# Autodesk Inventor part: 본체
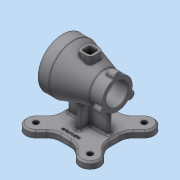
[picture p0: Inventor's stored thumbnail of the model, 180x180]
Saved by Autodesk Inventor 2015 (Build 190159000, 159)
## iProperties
Created: 2018-03
Part Number: 본체
Material: 일반
Document SubType Name: Modeling
Designer: SCD-A03
Density: 1 g/cm^3
Appearance: 기본값
Author: SCD-A03
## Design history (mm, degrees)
sketch "스케치1"
  geometry: L1 (50, 0)-(50, 45); L2 (50, 45)-(30, 45); L3 (30, 45)-(-27, 27.5); L4 (-50, 0)-(-50, 27.5); L5 (-27, 27.5)-(-50, 27.5); L6 (50, 0)-(-50, 0); L7 (0, 0)-(0, 7.405)
  constraints: 14 end point, 3 vertical, 2 horizontal, 1 perpendicular, 1 other
  dimensions: "d0" = 45 distance of L1.start L1.end; "d1" = 20 distance of L1.end L2.end; "d10" = 27.5 distance of L4.start L4.end; "d11" = 77 distance from line of L3.end L1; "d12" = 100 distance from line of L4.end L1; "d13" = 45 distance from line of L7.start L2; "d14" = 37.59532 distance from line of L7.end L2
revolve "회전1" sketch "스케치1" stored, may be unused: angle "d15" = 90 deg
node "작업 평면1"
sketch "스케치2"
  geometry: L1 (-19.544, 45)-(19.544, 45); L2 (45, 19.544)-(45, -19.544); L3 (-36.77, -36.77)-(-45, -45); L4 (-62.225, -36.77)-(-45, -19.544); L5 (19.544, 45)-(36.77, 62.225); L6 (-36.77, -62.225)-(-19.544, -45); L7 (45, 19.544)-(62.225, 36.77); L8 (45, 45)-(57.655, 57.655); L9 (-45, -45)-(-45, -32.068); L10 (-45, -19.544)-(-45, 19.544); L11 (-32.068, -45)-(-45, -45); L12 (62.225, -36.77)-(45, -19.544); L13 (-19.544, 45)-(-36.77, 62.225); L14 (45, -45)-(36.77, -36.77); L15 (-49.497, 49.497)-(-57.655, 57.655); L16 (36.77, -62.225)-(19.544, -45); L17 (-45, 19.544)-(-62.225, 36.77); L18 (-36.77, -36.77)-(-49.497, -49.497); L19 (-45, -45)-(-36.77, -36.77); L20 (45, -45)-(32.068, -45); L21 (19.544, -45)-(-19.544, -45); A1 r 18 centre (49.497, 49.497) between (62.225, 36.77) and (36.77, 62.225); A2 r 18 centre (49.497, -49.497) between (36.77, -62.225) and (62.225, -36.77); A3 r 18 centre (-49.497, 49.497) between (-36.77, 62.225) and (-62.225, 36.77); A4 r 18 centre (-49.497, -49.497) between (-62.225, -36.77) and (-36.77, -62.225); 1 further point
  constraints: 42 end point, 21 parallel, 8 point on circle, 4 centre point, 3 point on line, 1 coincident, 1 horizontal, 1 perpendicular
  dimensions: "d17" = 90 distance of L14.start L3.end; "d18" = 90 distance of L8.start L14.start; "d20" = 36 diameter of A1; "d25" = 36 diameter of A2
extrude "돌출1" join sketch "스케치2" distance "d28" = 12; taper "d29" = 0 deg
node "작업 평면2"
sketch "스케치3"
  geometry: L1 (-12.5, 12.5)-(12.5, 12.5); L2 (12.5, 12.5)-(12.5, -12.5); L3 (12.5, -12.5)-(-12.5, -12.5); L4 (-12.5, -12.5)-(-12.5, 12.5); L5 (-12.5, 12.5)-(12.5, -12.5); L6 (12.5, 12.5)-(-12.5, -12.5); 1 further point
  constraints: 12 end point, 2 midpoint, 2 parallel, 1 horizontal, 1 perpendicular
  dimensions: "d31" = 25 distance of L2.end L3.end; "d32" = 25 distance of L1.end L2.end
extrude "돌출2" join sketch "스케치3" stored distance "d33" = 12; taper "d34" = 0 deg
sketch "스케치4"
  geometry: L1 (-7.5, 7.5)-(7.5, 7.5); L2 (7.5, 7.5)-(7.5, -7.5); L3 (7.5, -7.5)-(-7.5, -7.5); L4 (-7.5, -7.5)-(-7.5, 7.5); L5 (-7.5, 7.5)-(7.5, -7.5); L6 (7.5, 7.5)-(-7.5, -7.5); 1 further point
  constraints: 12 end point, 2 midpoint, 2 parallel, 1 horizontal, 1 perpendicular
  dimensions: "d35" = 15 distance of L2.end L3.end; "d36" = 15 distance of L1.end L2.end
extrude "돌출3" cut sketch "스케치4" distance "d37" = 30; taper "d38" = 0 deg
sketch "스케치5"
  geometry: L1 (37, 4)-(-37, 4); L2 (-37, 4)-(-37, -4); L3 (-37, -4)-(37, -4); L4 (37, -4)-(37, 4); L5 (37, 4)-(-37, -4); L6 (-37, 4)-(37, -4); L7 (4, -24)-(-4, -24); L8 (-4, -24)-(-4, 24); L9 (-4, 24)-(4, 24); L10 (4, 24)-(4, -24); L11 (4, -24)-(-4, 24); L12 (-4, -24)-(4, 24); 1 further point
  constraints: 24 end point, 4 midpoint, 4 parallel, 2 horizontal, 2 perpendicular
  dimensions: "d39" = 8 distance of L8.end L9.end; "d40" = 8 distance of L3.end L1.start; "d41" = 74 distance of L2.end L3.end; "d42" = 48 distance of L9.end L7.start
extrude "돌출4" join sketch "스케치5" stored distance "d43" = 30; taper "d44" = 0 deg
sketch "스케치6"
  geometry: C1 r 7 at (-27.5, 0); 1 further point
  constraints: 1 centre point, 1 horizontal alignment, 1 other
  dimensions: "d46" = 14 diameter of C1
extrude "돌출5" join sketch "스케치6" distance "d47" = 15; taper "d48" = 0 deg
hole "구멍1" diameter "d54" = 3.242; stored, may be unused: countersink angle "d58" = 90 deg, drill point angle "d60" = 118 deg; dims "d52" = 10, "d53" = 10, "d55" = 9, "d56" = 4, "d57" = 2, "d59" = 11
sketch "스케치7"
  geometry: C1 r 45 at (0, 0) reference; 1 further point
  constraints: 1 horizontal alignment
  dimensions: "d64" = 40 distance of point (40, 0) C1.centre
hole "구멍2" sketch "스케치7" at (40, 0) diameter "d65" = 3.242; stored, may be unused: countersink angle "d69" = 90 deg, drill point angle "d71" = 118 deg; dims "d66" = 9, "d67" = 4, "d68" = 2, "d70" = 11
feature "면 기울기2" dims angle "d160" = 5 deg
hole "구멍3" diameter "d77" = 52; stored, may be unused: countersink angle "d81" = 90 deg, drill point angle "d83" = 0 deg; dims "d78" = 9, "d79" = 70, "d80" = 23, "d82" = 70, "d95" = 10, "d96" = 10
hole "구멍4" diameter "d88" = 40; stored, may be unused: countersink angle "d92" = 90 deg, drill point angle "d94" = 118 deg; dims "d86" = 10, "d87" = 10, "d89" = 9, "d90" = 70, "d91" = 23, "d93" = 70
hole "구멍5" diameter "d99" = 10; stored, may be unused: countersink angle "d103" = 90 deg, drill point angle "d105" = 118 deg; dims "d97" = 10, "d98" = 10, "d100" = 9, "d101" = 70, "d102" = 23, "d104" = 70
hole "구멍6" diameter "d108" = 10; stored, may be unused: countersink angle "d112" = 90 deg, drill point angle "d114" = 118 deg; dims "d106" = 10, "d107" = 10, "d109" = 9, "d110" = 70, "d111" = 23, "d113" = 70
hole "구멍7" diameter "d117" = 10; stored, may be unused: countersink angle "d121" = 90 deg, drill point angle "d123" = 118 deg; dims "d115" = 10, "d116" = 10, "d118" = 9, "d119" = 70, "d120" = 23, "d122" = 70
hole "구멍8" diameter "d126" = 10; stored, may be unused: countersink angle "d130" = 90 deg, drill point angle "d132" = 118 deg; dims "d124" = 10, "d125" = 10, "d127" = 9, "d128" = 70, "d129" = 23, "d131" = 70
sketch "스케치8"
  geometry: L1 (45, -19.544)-(45, 19.544) reference; 2 further points
  constraints: 1 other
  dimensions: "d133" = 35 distance of point (0, -35) point (0, 0); "d134" = 45 distance from line of point (0, -35) L1
feature "엠보싱1" sketch "스케치8" dims "d17" = 90, "d18" = 90, "d20" = 36, "d25" = 36, "d135" = 0.5, "d136" = 0
fillet "모깎기1" dims "d137" = 25
fillet "모깎기3" dims "d139" = 8
fillet "모깎기4" dims "d140" = 1
chamfer "모따기1" distance "d141" = 3; stored, may be unused: second distance "d142" = 2, angle "d143" = 45 deg
fillet "모깎기5" dims "d144" = 3
fillet "모깎기7" dims "d146" = 3
fillet "모깎기10" dims "d149" = 3
fillet "모깎기11" dims "d150" = 3
chamfer "모따기2" distance "d151" = 1; stored, may be unused: second distance "d152" = 2, angle "d153" = 45 deg
chamfer "모따기3" distance "d154" = 1; stored, may be unused: second distance "d155" = 2, angle "d156" = 45 deg
fillet "모깎기12" dims "d157" = 3
fillet "모깎기13" dims "d158" = 3
fillet "모깎기14" dims "d159" = 3
fillet "모깎기15" dims "d161" = 1
fillet "모깎기16" dims "d162" = 3
fillet "모깎기17" dims "d163" = 1
node "솔리드1"
pattern_circular "원형 패턴1" dims angle "d50" = 360 deg
pattern_circular "원형 패턴2" dims angle "d62" = 360 deg
pattern_circular "원형 패턴3" dims angle "d73" = 360 deg
other parameters: "d16" = -82, "d21" = 18, "d22" = 18, "d23" = 36, "d24" = 36, "d26" = 18, "d27" = 18, "d30" = 45
